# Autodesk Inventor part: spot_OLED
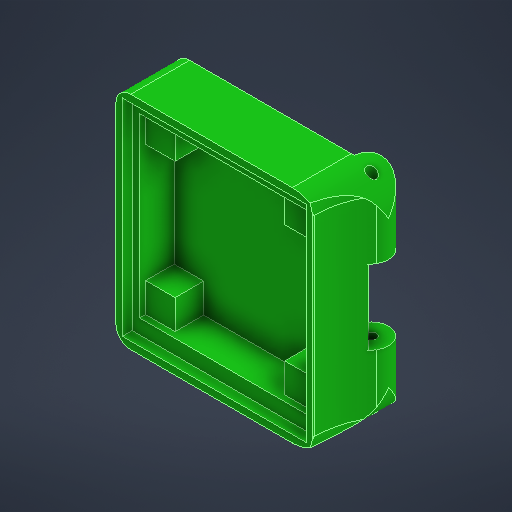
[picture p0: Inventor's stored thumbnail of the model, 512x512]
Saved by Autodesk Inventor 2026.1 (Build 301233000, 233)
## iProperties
Created: 2025-11
Part Number: spot_OLED
Material: Generico
Document SubType Name: Modeling
Designer: Gek
Density: 1 g/cm^3
Appearance: Verde scuro
Author: Gek
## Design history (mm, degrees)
sketch "Schizzo1"
  geometry: L1 (20, 22.5)-(-20, 22.5); L2 (-20, 22.5)-(-20, -22.5); L3 (-20, -22.5)-(20, -22.5); L4 (20, -22.5)-(20, 22.5); L5 (28, 0)-(-28, 0) reference; L6 (0, -31.5)-(0, 31.5) reference; 1 further point
  constraints: 8 end point, 2 parallel, 1 horizontal, 1 perpendicular, 2 other
  dimensions: "d0" = 40 distance of L1.start L1.end; "d1" = 45 distance of L3.end L1.start
extrude "Estrusione1" new body sketch "Schizzo1" distance "d2" = 12; taper "d3" = 0 deg
sketch "Schizzo2"
  geometry: L1 (-17.15, -18)-(17.15, -18); L2 (17.15, -18)-(17.15, 18); L3 (17.15, 18)-(-17.15, 18); L4 (-17.15, 18)-(-17.15, -18); L5 (0, -31.5)-(0, 31.5) reference; L6 (-28, 0)-(28, 0) reference; 1 further point
  constraints: 8 end point, 2 parallel, 1 horizontal, 1 perpendicular, 2 other
  dimensions: "d4" = 36 distance of L3.end L1.start; "d5" = 34.3 distance of L2.end L3.end
extrude "Estrusione2" cut sketch "Schizzo2" distance "d6" = 9; taper "d7" = 0 deg
sketch "Schizzo3"
  geometry: L1 (-17.15, -18)-(-17.15, 18) reference; L2 (-17.15, 18)-(-11.15, 18); L3 (-11.15, 18)-(-11.15, 12); L4 (-11.15, 12)-(-17.15, 12); L5 (-17.15, 12)-(-17.15, 18); L6 (17.15, 18)-(11.15, 18); L7 (11.15, 18)-(11.15, 12); L8 (11.15, 12)-(17.15, 12); L9 (17.15, 12)-(17.15, 18); L10 (17.15, -18)-(11.15, -18); L11 (11.15, -18)-(11.15, -12); L12 (11.15, -12)-(17.15, -12); L13 (17.15, -12)-(17.15, -18); L14 (17.15, -18)-(-17.15, -18) reference; L15 (-17.15, -18)-(-11.15, -18); L16 (-11.15, -18)-(-11.15, -12); L17 (-11.15, -12)-(-17.15, -12); L18 (-17.15, -12)-(-17.15, -18); L19 (17.15, 18)-(17.15, -18) reference; L20 (17.15, -18)-(-17.15, -18) reference; 4 further points
  constraints: 32 end point, 8 parallel, 6 equal length, 4 horizontal, 4 perpendicular, 3 point on line, 2 collinear
  dimensions: "d8" = 6 distance of L2.end L3.end
extrude "Estrusione3" join sketch "Schizzo3" distance "d9" = 5.8; taper "d10" = 0 deg
sketch "Schizzo4"
  geometry: L1 (-18.7, -21)-(18.7, -21); L2 (18.7, -21)-(18.7, 21); L3 (18.7, 21)-(-18.7, 21); L4 (-18.7, 21)-(-18.7, -21); L5 (-18.7, -21)-(18.7, 21); L6 (18.7, -21)-(-18.7, 21); L7 (-20, -22.5)-(-20, 22.5) reference; L8 (20, -22.5)-(-20, -22.5) reference; 1 further point
  constraints: 12 end point, 2 midpoint, 2 parallel, 1 horizontal, 1 perpendicular
  dimensions: "d11" = 1.3 distance between parallel lines of L7 L4; "d16" = 37.4 distance between parallel lines of L4 L2 (derived); "d17" = 42 distance between parallel lines of L3 L1
extrude "Estrusione4" cut sketch "Schizzo4" distance "d13" = 2; taper "d14" = 0 deg
fillet "Raccordo1" dims "d18" = 3
sketch "Schizzo6"
  geometry: L1 (0, 0)-(0, 12) reference; C1 r 3.5 at (0, 12); 1 further point
  constraints: 1 centre point
  dimensions: "d22" = 7 diameter of C1
extrude "Estrusione6" join sketch "Schizzo6" stored distance "d23" = 10; taper "d24" = 0 deg
sketch "Schizzo7"
  geometry: C1 r 1 at (0, 12); A1 r 3.5 centre (0, 12) between (3.5, 12) and (3, 10.197) reference; 2 further points
  constraints: 1 centre point, 1 coincident
  dimensions: "d25" = 2 diameter of C1
extrude "Estrusione7" cut sketch "Schizzo7" extent not by distance; stored distance "d26" = 0; taper "d27" = 0 deg
sketch "Schizzo8"
  geometry: C1 r 1 at (20, 12) reference; C2 r 3.75 at (20, 12); 1 further point
  constraints: 1 centre point, 1 coincident
  dimensions: "d28" = 7.5 diameter of C2
extrude "Estrusione8" cut sketch "Schizzo8" stored distance "d29" = 15.2; taper "d30" = 0 deg
sketch "Schizzo9"
  geometry: L1 (16.25, -7.6)-(16.25, 7.6) reference; L2 (16.25, -7.6)-(13.25, -7.6); L3 (13.25, -7.6)-(13.25, 7.6); L4 (13.25, 7.6)-(16.25, 7.6); L5 (16.25, 7.6)-(16.25, -7.6); L6 (16.25, 7.6)-(16.5, 7.6) reference; 2 further points
  constraints: 8 end point, 2 parallel, 1 collinear, 1 horizontal, 1 perpendicular
  dimensions: "d31" = 3 distance of L3.end L4.end
extrude "Estrusione9" cut sketch "Schizzo9" distance "d32" = 5.45; taper "d33" = 0 deg
chamfer "Smusso1" distance "d34" = 2; stored, may be unused: second distance "d35" = 2, angle "d36" = 45 deg
fillet "Raccordo2" dims "d37" = 17.75
sketch "Schizzo10"
  geometry: L1 (16.5, -22.5)-(-17, -22.5) reference; L2 (23.5, -22.5)-(23.5, -7.6) reference; L3 (19.122, -22.5)-(-17, -22.5) reference; L4 (16.5, -22.5)-(23.5, -22.5); L5 (23.5, -14.9)-(23.5, -22.5); A1 r 7.6 centre (15.9, -14.9) between (15.9, -22.5) and (23.5, -14.9); 2 further points
  constraints: 4 end point, 3 tangent, 2 point on circle, 2 point on line, 1 centre point, 1 collinear, 1 perpendicular
extrude "Estrusione10" cut sketch "Schizzo10" extent not by distance; stored distance "d38" = 0; taper "d39" = 0 deg
mirror "Speculare1"
sketch "Schizzo11"
  geometry: L1 (-20, 12)-(-20, 0) reference; C1 r 1 at (-20, 12); 1 further point
  constraints: 1 centre point
  dimensions: "d40" = 2 diameter of C1
extrude "Estrusione11" cut sketch "Schizzo11" stored distance "d41" = 10; taper "d42" = 0 deg
fillet "Raccordo3" dims "d43" = 1
node "Solido1"
